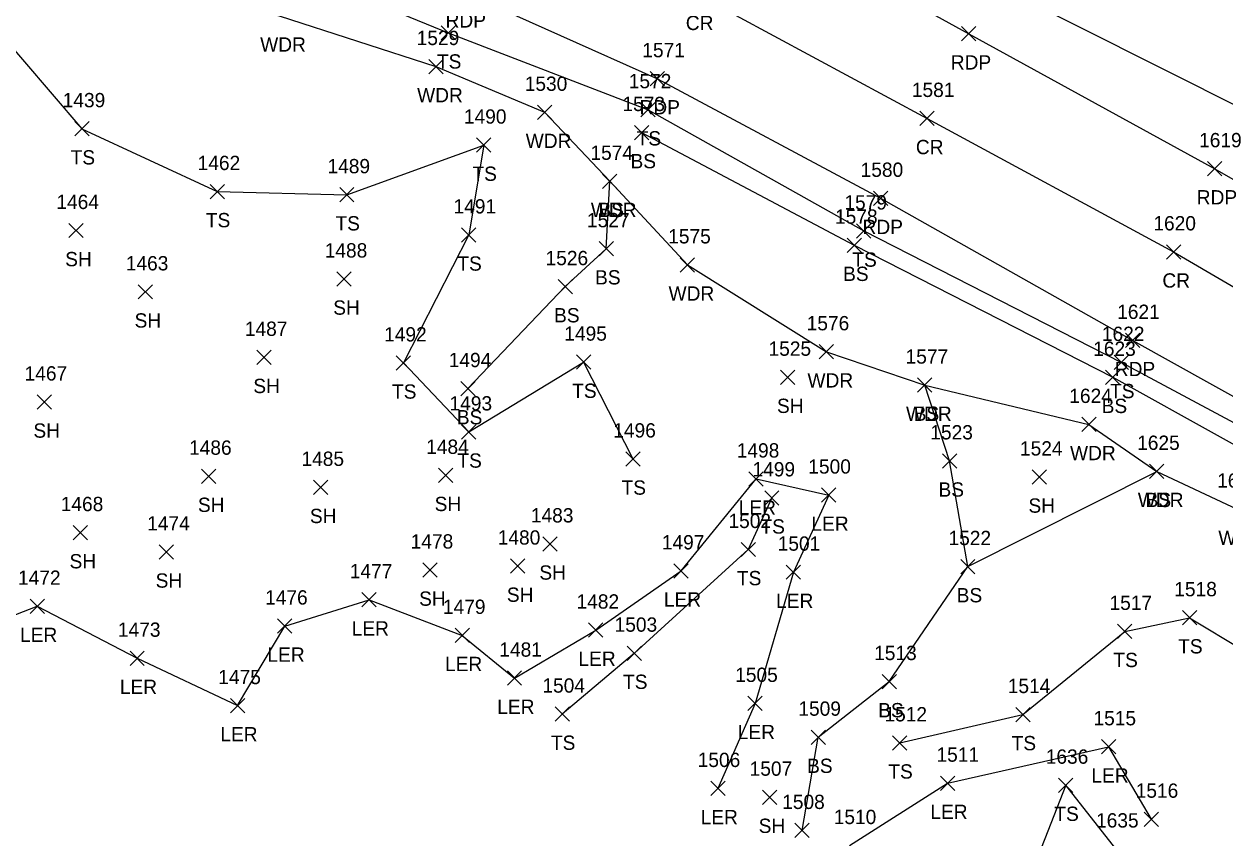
# Model space of a CAD drawing. Extents: x 1586965 to 1590952, y 716317 to 720029.
# Drawn here: x 1587807.3 to 1587975.1, y 719689.6 to 719803.4 of the extents above; entities that cross this region are included whole.
import ezdxf

# ---------------------------------------------------------------- set-up
doc = ezdxf.new("R2010")
doc.units = 0
for name, color, linetype in [('L_A', 7, 'Continuous'), ('L_I', 7, 'Continuous'), ('L_TIC', 7, 'Continuous'), ('LARO', 7, 'Continuous'), ('LAWA', 7, 'Continuous'), ('LELB', 7, 'Continuous'), ('P_A', 7, 'Continuous'), ('P_I', 7, 'Continuous'), ('P_TIC', 7, 'Continuous'), ('PET', 7, 'Continuous'), ('PRC', 7, 'Continuous')]:
    doc.layers.add(name, color=color, linetype=linetype)

msp = doc.modelspace()

# ---------------------------------------------------------------- linework, layer by layer
at = {"layer": 'L_TIC'}
for points in [[(1587865.59, 719801.16), (1587867.59, 719803.16)], [(1587867.59, 719801.16), (1587865.59, 719803.16)], [(1587863.87, 719796.45), (1587865.87, 719798.45)], [(1587865.87, 719796.45), (1587863.87, 719798.45)], [(1587879.05, 719790.05), (1587881.05, 719792.05)], [(1587881.05, 719790.05), (1587879.05, 719792.05)], [(1587893.5, 719790.41), (1587895.5, 719792.41)], [(1587895.5, 719790.41), (1587893.5, 719792.41)], [(1587814.4, 719787.75), (1587816.4, 719789.75)], [(1587816.4, 719787.75), (1587814.4, 719789.75)], [(1587892.61, 719787.22), (1587894.61, 719789.22)], [(1587894.61, 719787.22), (1587892.61, 719789.22)], [(1587870.55, 719785.46), (1587872.55, 719787.46)], [(1587872.55, 719785.46), (1587870.55, 719787.46)], [(1587888.14, 719780.4), (1587890.14, 719782.4)], [(1587890.14, 719780.4), (1587888.14, 719782.4)], [(1587888.14, 719780.4), (1587890.14, 719782.4)], [(1587890.14, 719780.4), (1587888.14, 719782.4)], [(1587833.3, 719778.97), (1587835.3, 719780.97)], [(1587835.3, 719778.97), (1587833.3, 719780.97)], [(1587851.41, 719778.52), (1587853.41, 719780.52)], [(1587853.41, 719778.52), (1587851.41, 719780.52)], [(1587813.56, 719773.52), (1587815.56, 719775.52)], [(1587815.56, 719773.52), (1587813.56, 719775.52)], [(1587868.44, 719772.9), (1587870.44, 719774.9)], [(1587870.44, 719772.9), (1587868.44, 719774.9)], [(1587923.64, 719773.45), (1587925.64, 719775.45)], [(1587925.64, 719773.45), (1587923.64, 719775.45)], [(1587887.66, 719770.97), (1587889.66, 719772.97)], [(1587889.66, 719770.97), (1587887.66, 719772.97)], [(1587922.32, 719771.46), (1587924.32, 719773.46)], [(1587924.32, 719771.46), (1587922.32, 719773.46)], [(1587899.01, 719768.71), (1587901.01, 719770.71)], [(1587901.01, 719768.71), (1587899.01, 719770.71)], [(1587851.02, 719766.74), (1587853.02, 719768.74)], [(1587853.02, 719766.74), (1587851.02, 719768.74)], [(1587881.93, 719765.67), (1587883.93, 719767.67)], [(1587883.93, 719765.67), (1587881.93, 719767.67)], [(1587823.26, 719764.94), (1587825.26, 719766.94)], [(1587825.26, 719764.94), (1587823.26, 719766.94)], [(1587839.85, 719755.78), (1587841.85, 719757.78)], [(1587841.85, 719755.78), (1587839.85, 719757.78)], [(1587918.42, 719756.56), (1587920.42, 719758.56)], [(1587920.42, 719756.56), (1587918.42, 719758.56)], [(1587859.31, 719755), (1587861.31, 719757)], [(1587861.31, 719755), (1587859.31, 719757)], [(1587884.49, 719755.11), (1587886.49, 719757.11)], [(1587886.49, 719755.11), (1587884.49, 719757.11)], [(1587959.66, 719755.07), (1587961.66, 719757.07)], [(1587961.66, 719755.07), (1587959.66, 719757.07)], [(1587913.03, 719753), (1587915.03, 719755)], [(1587915.03, 719753), (1587913.03, 719755)], [(1587958.45, 719752.99), (1587960.45, 719754.99)], [(1587960.45, 719752.99), (1587958.45, 719754.99)], [(1587868.34, 719751.41), (1587870.34, 719753.41)], [(1587870.34, 719751.41), (1587868.34, 719753.41)], [(1587932.18, 719751.9), (1587934.18, 719753.9)], [(1587934.18, 719751.9), (1587932.18, 719753.9)], [(1587932.18, 719751.9), (1587934.18, 719753.9)], [(1587934.18, 719751.9), (1587932.18, 719753.9)], [(1587809.12, 719749.54), (1587811.12, 719751.54)], [(1587811.12, 719749.54), (1587809.12, 719751.54)], [(1587955.11, 719746.4), (1587957.11, 719748.4)], [(1587957.11, 719746.4), (1587955.11, 719748.4)], [(1587868.45, 719745.35), (1587870.45, 719747.35)], [(1587870.45, 719745.35), (1587868.45, 719747.35)], [(1587891.39, 719741.57), (1587893.39, 719743.57)], [(1587893.39, 719741.57), (1587891.39, 719743.57)], [(1587935.65, 719741.3), (1587937.65, 719743.3)], [(1587937.65, 719741.3), (1587935.65, 719743.3)], [(1587832.11, 719739.16), (1587834.11, 719741.16)], [(1587834.11, 719739.16), (1587832.11, 719741.16)], [(1587865.2, 719739.28), (1587867.2, 719741.28)], [(1587867.2, 719739.28), (1587865.2, 719741.28)], [(1587948.17, 719739.05), (1587950.17, 719741.05)], [(1587950.17, 719739.05), (1587948.17, 719741.05)], [(1587964.59, 719739.84), (1587966.59, 719741.84)], [(1587966.59, 719739.84), (1587964.59, 719741.84)], [(1587964.59, 719739.84), (1587966.59, 719741.84)], [(1587966.59, 719739.84), (1587964.59, 719741.84)], [(1587847.76, 719737.6), (1587849.76, 719739.6)], [(1587849.76, 719737.6), (1587847.76, 719739.6)], [(1587908.6, 719738.77), (1587910.6, 719740.77)], [(1587910.6, 719738.77), (1587908.6, 719740.77)], [(1587910.8, 719736.13), (1587912.8, 719738.13)], [(1587912.8, 719736.13), (1587910.8, 719738.13)], [(1587918.76, 719736.52), (1587920.76, 719738.52)], [(1587920.76, 719736.52), (1587918.76, 719738.52)], [(1587814.17, 719731.27), (1587816.17, 719733.27)], [(1587816.17, 719731.27), (1587814.17, 719733.27)], [(1587879.82, 719729.69), (1587881.82, 719731.69)], [(1587881.82, 719729.69), (1587879.82, 719731.69)], [(1587907.51, 719728.91), (1587909.51, 719730.91)], [(1587909.51, 719728.91), (1587907.51, 719730.91)], [(1587826.2, 719728.57), (1587828.2, 719730.57)], [(1587828.2, 719728.57), (1587826.2, 719730.57)], [(1587863.02, 719726.04), (1587865.02, 719728.04)], [(1587865.02, 719726.04), (1587863.02, 719728.04)], [(1587875.28, 719726.59), (1587877.28, 719728.59)], [(1587877.28, 719726.59), (1587875.28, 719728.59)], [(1587898.12, 719725.92), (1587900.12, 719727.92)], [(1587900.12, 719725.92), (1587898.12, 719727.92)], [(1587913.82, 719725.74), (1587915.82, 719727.74)], [(1587915.82, 719725.74), (1587913.82, 719727.74)], [(1587938.19, 719726.52), (1587940.19, 719728.52)], [(1587940.19, 719726.52), (1587938.19, 719728.52)], [(1587938.19, 719726.52), (1587940.19, 719728.52)], [(1587940.19, 719726.52), (1587938.19, 719728.52)], [(1587808.15, 719720.97), (1587810.15, 719722.97)], [(1587810.15, 719720.97), (1587808.15, 719722.97)], [(1587854.51, 719721.88), (1587856.51, 719723.88)], [(1587856.51, 719721.88), (1587854.51, 719723.88)], [(1587969.17, 719719.37), (1587971.17, 719721.37)], [(1587971.17, 719719.37), (1587969.17, 719721.37)], [(1587842.73, 719718.21), (1587844.73, 719720.21)], [(1587844.73, 719718.21), (1587842.73, 719720.21)], [(1587886.2, 719717.64), (1587888.2, 719719.64)], [(1587888.2, 719717.64), (1587886.2, 719719.64)], [(1587960.12, 719717.46), (1587962.12, 719719.46)], [(1587962.12, 719717.46), (1587960.12, 719719.46)], [(1587867.54, 719716.9), (1587869.54, 719718.9)], [(1587869.54, 719716.9), (1587867.54, 719718.9)], [(1587822.11, 719713.7), (1587824.11, 719715.7)], [(1587824.11, 719713.7), (1587822.11, 719715.7)], [(1587891.6, 719714.41), (1587893.6, 719716.41)], [(1587893.6, 719714.41), (1587891.6, 719716.41)], [(1587874.84, 719710.92), (1587876.84, 719712.92)], [(1587876.84, 719710.92), (1587874.84, 719712.92)], [(1587927.22, 719710.44), (1587929.22, 719712.44)], [(1587929.22, 719710.44), (1587927.22, 719712.44)], [(1587836.15, 719707.08), (1587838.15, 719709.08)], [(1587838.15, 719707.08), (1587836.15, 719709.08)], [(1587908.45, 719707.39), (1587910.45, 719709.39)], [(1587910.45, 719707.39), (1587908.45, 719709.39)], [(1587881.52, 719705.89), (1587883.52, 719707.89)], [(1587883.52, 719705.89), (1587881.52, 719707.89)], [(1587945.9, 719705.83), (1587947.9, 719707.83)], [(1587947.9, 719705.83), (1587945.9, 719707.83)], [(1587917.29, 719702.66), (1587919.29, 719704.66)], [(1587919.29, 719702.66), (1587917.29, 719704.66)], [(1587928.67, 719701.87), (1587930.67, 719703.87)], [(1587930.67, 719701.87), (1587928.67, 719703.87)], [(1587957.87, 719701.32), (1587959.87, 719703.32)], [(1587959.87, 719701.32), (1587957.87, 719703.32)], [(1587903.27, 719695.49), (1587905.27, 719697.49)], [(1587905.27, 719695.49), (1587903.27, 719697.49)], [(1587935.37, 719696.23), (1587937.37, 719698.23)], [(1587937.37, 719696.23), (1587935.37, 719698.23)], [(1587951.87, 719695.95), (1587953.87, 719697.95)], [(1587953.87, 719695.95), (1587951.87, 719697.95)], [(1587910.48, 719694.27), (1587912.48, 719696.27)], [(1587912.48, 719694.27), (1587910.48, 719696.27)], [(1587963.83, 719691.19), (1587965.83, 719693.19)], [(1587965.83, 719691.19), (1587963.83, 719693.19)], [(1587915.02, 719689.62), (1587917.02, 719691.62)], [(1587917.02, 719689.62), (1587915.02, 719691.62)]]:
    msp.add_lwpolyline(points, dxfattribs=at)
at = {"layer": 'LARO'}
for points in [[(1587800.16, 719718.5), (1587809.15, 719721.97), (1587823.11, 719714.7), (1587837.15, 719708.08), (1587843.73, 719719.21), (1587855.51, 719722.88), (1587868.54, 719717.9), (1587875.84, 719711.92), (1587887.2, 719718.64), (1587899.12, 719726.92), (1587909.6, 719739.77), (1587919.76, 719737.52), (1587914.82, 719726.74), (1587909.45, 719708.39), (1587904.27, 719696.49)], [(1587922.67, 719688.51), (1587936.37, 719697.23), (1587958.87, 719702.32), (1587964.83, 719692.19)]]:
    msp.add_lwpolyline(points, dxfattribs=at)
at = {"layer": 'LAWA'}
msp.add_lwpolyline([(1587792.66, 719819.32), (1587813.67, 719812.11), (1587842.94, 719804.53), (1587864.87, 719797.45), (1587880.05, 719791.05), (1587889.14, 719781.4), (1587900.01, 719769.71), (1587919.42, 719757.56), (1587933.18, 719752.9), (1587956.11, 719747.4), (1587965.59, 719740.84), (1587976.83, 719735.56), (1587989.17, 719727.65), (1588001.34, 719721.18), (1588025.48, 719708.03), (1588041.3, 719690.98), (1588054.29, 719686.88), (1588082.98, 719668.28), (1588093.79, 719656.56), (1588121.25, 719657.28), (1588128.24, 719644.6), (1588131.95, 719613.69), (1588124.34, 719595.05)], dxfattribs=at)
at = {"layer": 'LELB'}
for points in [[(1587785.92, 719905.04), (1587790.72, 719880.4), (1587795.97, 719870.23), (1587799.98, 719865.36), (1587821.67, 719859.64), (1587858.86, 719846.91), (1587879.62, 719839.86), (1587909.63, 719826.79), (1587942.7, 719809.1), (1587978.02, 719791.31), (1588014.84, 719771.38), (1588022.21, 719777.17), (1588033.93, 719779.83), (1588041.77, 719778.33), (1588050.57, 719796.18), (1588059.09, 719817.76), (1588066.51, 719841.34), (1588067.52, 719856.77)], [(1587785.92, 719905.04), (1587790.72, 719880.4), (1587795.97, 719870.23), (1587799.98, 719865.36), (1587821.67, 719859.64), (1587858.86, 719846.91), (1587879.62, 719839.86), (1587909.63, 719826.79), (1587942.7, 719809.1), (1587978.02, 719791.31), (1588014.84, 719771.38), (1588022.21, 719777.17), (1588033.93, 719779.83), (1588041.77, 719778.33), (1588050.57, 719796.18), (1588059.09, 719817.76), (1588066.51, 719841.34), (1588067.52, 719856.77)], [(1587769.54, 719828.25), (1587817.81, 719818.92), (1587845.39, 719810.87), (1587866.59, 719802.16), (1587894.5, 719791.41), (1587924.64, 719774.45), (1587960.66, 719756.07), (1587994.24, 719738.05), (1588029.81, 719715.93), (1588049.13, 719705.79), (1588061.35, 719699.86), (1588090.7, 719682.25), (1588125.12, 719667.08), (1588163.84, 719653.66), (1588168.64, 719652.01), (1588170.5, 719647.84), (1588169.34, 719638.56), (1588158.94, 719617.68), (1588144.69, 719590.38)], [(1587769.54, 719828.25), (1587817.81, 719818.92), (1587845.39, 719810.87), (1587866.59, 719802.16), (1587894.5, 719791.41), (1587924.64, 719774.45), (1587960.66, 719756.07), (1587994.24, 719738.05), (1588029.81, 719715.93), (1588049.13, 719705.79), (1588061.35, 719699.86), (1588090.7, 719682.25), (1588125.12, 719667.08), (1588163.84, 719653.66), (1588168.64, 719652.01), (1588170.5, 719647.84), (1588169.34, 719638.56), (1588158.94, 719617.68), (1588144.69, 719590.38)], [(1587802.88, 719803.26), (1587815.4, 719788.75), (1587834.3, 719779.97), (1587852.41, 719779.52), (1587871.55, 719786.46), (1587869.44, 719773.9), (1587860.31, 719756), (1587869.45, 719746.35), (1587885.49, 719756.11), (1587892.39, 719742.57)], [(1587802.88, 719803.26), (1587815.4, 719788.75), (1587834.3, 719779.97), (1587852.41, 719779.52), (1587871.55, 719786.46), (1587869.44, 719773.9), (1587860.31, 719756), (1587869.45, 719746.35), (1587885.49, 719756.11), (1587892.39, 719742.57)], [(1587893.61, 719788.22), (1587923.32, 719772.46), (1587959.45, 719753.99), (1587990.31, 719736.86), (1587992.49, 719736.59), (1587993.47, 719735.49), (1587996.7, 719733.15), (1588001.37, 719729.89), (1588028.07, 719713.52), (1588047.21, 719701.72), (1588059.27, 719695.66), (1588101.54, 719672.79), (1588123.97, 719663.55), (1588153.31, 719655.21), (1588167.62, 719650.14)], [(1587893.61, 719788.22), (1587923.32, 719772.46), (1587959.45, 719753.99), (1587990.31, 719736.86), (1587992.49, 719736.59), (1587993.47, 719735.49), (1587996.7, 719733.15), (1588001.37, 719729.89), (1588028.07, 719713.52), (1588047.21, 719701.72), (1588059.27, 719695.66), (1588101.54, 719672.79), (1588123.97, 719663.55), (1588153.31, 719655.21), (1588167.62, 719650.14)], [(1587869.34, 719752.41), (1587882.93, 719766.67), (1587888.66, 719771.97), (1587889.14, 719781.4)], [(1587869.34, 719752.41), (1587882.93, 719766.67), (1587888.66, 719771.97), (1587889.14, 719781.4)], [(1587939.19, 719727.52), (1587936.65, 719742.3), (1587933.18, 719752.9)], [(1587939.19, 719727.52), (1587936.65, 719742.3), (1587933.18, 719752.9)], [(1587916.02, 719690.62), (1587918.29, 719703.66), (1587928.22, 719711.44), (1587939.19, 719727.52), (1587965.59, 719740.84)], [(1587916.02, 719690.62), (1587918.29, 719703.66), (1587928.22, 719711.44), (1587939.19, 719727.52), (1587965.59, 719740.84)], [(1587911.8, 719737.13), (1587908.51, 719729.91), (1587892.6, 719715.41), (1587882.52, 719706.89)], [(1587911.8, 719737.13), (1587908.51, 719729.91), (1587892.6, 719715.41), (1587882.52, 719706.89)], [(1587929.67, 719702.87), (1587946.9, 719706.83), (1587961.12, 719718.46), (1587970.17, 719720.37), (1587977.76, 719715.8), (1587982.6, 719715.23), (1587982.22, 719704.04)], [(1587929.67, 719702.87), (1587946.9, 719706.83), (1587961.12, 719718.46), (1587970.17, 719720.37), (1587977.76, 719715.8), (1587982.6, 719715.23), (1587982.22, 719704.04)], [(1587969.24, 719671.97), (1587959.85, 719688.03), (1587952.87, 719696.95), (1587946.92, 719681.69)], [(1587969.24, 719671.97), (1587959.85, 719688.03), (1587952.87, 719696.95), (1587946.92, 719681.69)]]:
    msp.add_lwpolyline(points, dxfattribs=at)
at = {"layer": 'P_TIC'}
for points in [[(1587938.32, 719801.03), (1587940.32, 719803.03)], [(1587940.32, 719801.03), (1587938.32, 719803.03)], [(1587894.82, 719794.75), (1587896.82, 719796.75)], [(1587896.82, 719794.75), (1587894.82, 719796.75)], [(1587932.49, 719789.19), (1587934.49, 719791.19)], [(1587934.49, 719789.19), (1587932.49, 719791.19)], [(1587972.69, 719782.16), (1587974.69, 719784.16)], [(1587974.69, 719782.16), (1587972.69, 719784.16)], [(1587925.99, 719778.02), (1587927.99, 719780.02)], [(1587927.99, 719778.02), (1587925.99, 719780.02)], [(1587966.95, 719770.53), (1587968.95, 719772.53)], [(1587968.95, 719770.53), (1587966.95, 719772.53)], [(1587961.24, 719758.15), (1587963.24, 719760.15)], [(1587963.24, 719758.15), (1587961.24, 719760.15)]]:
    msp.add_lwpolyline(points, dxfattribs=at)
at = {"layer": 'PET'}
for points in [[(1587795.98, 719858.74), (1587820.3, 719853.13), (1587857.37, 719841.42), (1587877.69, 719833.83), (1587907.04, 719819.84), (1587939.32, 719802.03), (1587973.69, 719783.16), (1588008.21, 719763.34), (1588019.61, 719757.58), (1588045.18, 719744.38), (1588072.84, 719731.02), (1588081.8, 719723.85), (1588104.43, 719712.22), (1588133.68, 719697.26), (1588170.87, 719681.39), (1588198.42, 719670.99), (1588228.28, 719659.25)], [(1587769.59, 719834.05), (1587819.16, 719826.14), (1587848.36, 719816.77), (1587868.73, 719807.9), (1587895.82, 719795.75), (1587926.99, 719779.02), (1587962.24, 719759.15), (1587995.65, 719740.56), (1588031.83, 719719.54), (1588060.89, 719703.68), (1588093.53, 719688.06), (1588127.35, 719672.7), (1588165.1, 719657.02), (1588195.68, 719645.12), (1588212.38, 719637.86), (1588219.86, 719635.29)]]:
    msp.add_lwpolyline(points, dxfattribs=at)
at = {"layer": 'PRC'}
msp.add_lwpolyline([(1587770.57, 719846.88), (1587822.37, 719838.71), (1587852.49, 719828.95), (1587873.58, 719820.04), (1587901.35, 719807.55), (1587933.49, 719790.19), (1587967.95, 719771.53), (1588001.84, 719751.71), (1588038.72, 719731.7), (1588068.79, 719715.56), (1588099.02, 719700.65), (1588127.2, 719686.75), (1588167.73, 719669.46), (1588194.58, 719658.84), (1588224.51, 719647.27)], dxfattribs=at)
msp.add_lwpolyline([(1587770.57, 719846.88), (1587822.37, 719838.71), (1587852.49, 719828.95), (1587873.58, 719820.04), (1587901.35, 719807.55), (1587933.49, 719790.19), (1587967.95, 719771.53), (1588001.84, 719751.71), (1588038.72, 719731.7), (1588068.79, 719715.56), (1588099.02, 719700.65), (1588127.2, 719686.75), (1588167.73, 719669.46), (1588194.58, 719658.84), (1588224.51, 719647.27)], dxfattribs=at)

# ---------------------------------------------------------------- texts
at = {"layer": 'L_A'}
for s, p in [('WDR', (1587840.3, 719799.53)), ('TS', (1587865, 719797.16)), ('WDR', (1587862.23, 719792.45)), ('WDR', (1587877.41, 719786.05)), ('TS', (1587892.91, 719786.41)), ('TS', (1587813.81, 719783.75)), ('BS', (1587892.05, 719783.22)), ('TS', (1587869.96, 719781.46)), ('WDR', (1587886.51, 719776.4)), ('BS', (1587887.58, 719776.4)), ('TS', (1587832.71, 719774.97)), ('TS', (1587850.82, 719774.52)), ('SH', (1587813.05, 719769.52)), ('TS', (1587923.05, 719769.45)), ('TS', (1587867.85, 719768.9)), ('BS', (1587921.76, 719767.46)), ('BS', (1587887.1, 719766.97)), ('WDR', (1587897.37, 719764.71)), ('SH', (1587850.51, 719762.74)), ('SH', (1587822.75, 719760.94)), ('BS', (1587881.37, 719761.67)), ('WDR', (1587916.78, 719752.56)), ('SH', (1587839.34, 719751.78)), ('TS', (1587858.72, 719751)), ('TS', (1587883.9, 719751.11)), ('TS', (1587959.07, 719751.07)), ('SH', (1587912.52, 719749)), ('BS', (1587957.89, 719748.99)), ('BS', (1587867.78, 719747.41)), ('WDR', (1587930.55, 719747.9)), ('BS', (1587931.62, 719747.9)), ('SH', (1587808.61, 719745.54)), ('WDR', (1587953.47, 719742.4)), ('TS', (1587867.86, 719741.35)), ('TS', (1587890.8, 719737.57)), ('BS', (1587935.09, 719737.3)), ('WDR', (1587962.95, 719735.84)), ('BS', (1587964.03, 719735.84)), ('SH', (1587831.6, 719735.16)), ('SH', (1587864.68, 719735.28)), ('LER', (1587907.18, 719734.77)), ('SH', (1587947.66, 719735.05)), ('SH', (1587847.25, 719733.6)), ('TS', (1587910.21, 719732.13)), ('LER', (1587917.34, 719732.52)), ('WDR', (1587974.19, 719730.56)), ('SH', (1587813.66, 719727.27)), ('SH', (1587879.31, 719725.69)), ('SH', (1587825.69, 719724.57)), ('TS', (1587906.92, 719724.91)), ('SH', (1587862.51, 719722.04)), ('SH', (1587874.77, 719722.59)), ('BS', (1587937.63, 719722.52)), ('BS', (1587937.63, 719722.52)), ('LER', (1587896.71, 719721.92)), ('LER', (1587912.4, 719721.74)), ('LER', (1587853.09, 719717.88)), ('LER', (1587806.74, 719716.97)), ('TS', (1587968.58, 719715.37)), ('LER', (1587841.32, 719714.21)), ('LER', (1587884.78, 719713.64)), ('LER', (1587866.13, 719712.9)), ('TS', (1587959.53, 719713.46)), ('TS', (1587891.01, 719710.41)), ('LER', (1587820.69, 719709.7)), ('LER', (1587873.43, 719706.92)), ('BS', (1587926.66, 719706.44)), ('LER', (1587834.73, 719703.08)), ('TS', (1587880.93, 719701.89)), ('LER', (1587907.04, 719703.39)), ('TS', (1587945.31, 719701.83)), ('BS', (1587916.73, 719698.66)), ('TS', (1587928.08, 719697.87)), ('LER', (1587956.46, 719697.32)), ('LER', (1587933.95, 719692.23)), ('TS', (1587951.28, 719691.95)), ('LER', (1587901.85, 719691.49)), ('SH', (1587909.96, 719690.27))]:
    msp.add_text(s, height=2, dxfattribs=at).set_placement(p)
at = {"layer": 'L_I'}
for s, p in [('1529', (1587862.17, 719800.45)), ('1572', (1587891.81, 719794.41)), ('1530', (1587877.27, 719794.05)), ('1439', (1587812.7, 719791.75)), ('1573', (1587890.92, 719791.22)), ('1490', (1587868.77, 719789.46)), ('1574', (1587886.45, 719784.4)), ('1574', (1587886.45, 719784.4)), ('1462', (1587831.56, 719782.97)), ('1489', (1587849.71, 719782.52)), ('1464', (1587811.82, 719777.52)), ('1579', (1587921.94, 719777.45)), ('1491', (1587867.32, 719776.9)), ('1527', (1587885.97, 719774.97)), ('1578', (1587920.63, 719775.46)), ('1575', (1587897.32, 719772.71)), ('1488', (1587849.32, 719770.74)), ('1526', (1587880.18, 719769.67)), ('1463', (1587821.52, 719768.94)), ('1487', (1587838.16, 719759.78)), ('1492', (1587857.62, 719759)), ('1495', (1587882.8, 719759.11)), ('1576', (1587916.67, 719760.56)), ('1622', (1587957.92, 719759.07)), ('1525', (1587911.34, 719757)), ('1577', (1587930.49, 719755.9)), ('1577', (1587930.49, 719755.9)), ('1623', (1587956.71, 719756.99)), ('1494', (1587866.65, 719755.41)), ('1467', (1587807.38, 719753.54)), ('1493', (1587866.76, 719749.35)), ('1624', (1587953.37, 719750.4)), ('1496', (1587889.64, 719745.57)), ('1523', (1587933.95, 719745.3)), ('1625', (1587962.85, 719743.84)), ('1625', (1587962.85, 719743.84)), ('1486', (1587830.36, 719743.16)), ('1484', (1587863.5, 719743.28)), ('1498', (1587906.9, 719742.77)), ('1524', (1587946.48, 719743.05)), ('1485', (1587846.07, 719741.6)), ('1500', (1587916.9, 719740.52)), ('1499', (1587909.1, 719740.13)), ('1626', (1587974.03, 719738.56)), ('1468', (1587812.43, 719735.27)), ('1474', (1587824.51, 719732.57)), ('1483', (1587878.13, 719733.69)), ('1502', (1587905.74, 719732.91)), ('1480', (1587873.5, 719730.59)), ('1522', (1587936.49, 719730.52)), ('1522', (1587936.49, 719730.52)), ('1478', (1587861.33, 719730.04)), ('1497', (1587896.43, 719729.92)), ('1501', (1587912.62, 719729.74)), ('1477', (1587852.82, 719725.88)), ('1472', (1587806.46, 719724.97)), ('1476', (1587840.99, 719722.21)), ('1518', (1587968.04, 719723.37)), ('1479', (1587865.84, 719720.9)), ('1482', (1587884.51, 719721.64)), ('1517', (1587958.99, 719721.46)), ('1473', (1587820.42, 719717.7)), ('1503', (1587889.83, 719718.41)), ('1481', (1587873.72, 719714.92)), ('1513', (1587926.1, 719714.44)), ('1475', (1587834.45, 719711.08)), ('1505', (1587906.68, 719711.39)), ('1504', (1587879.74, 719709.89)), ('1514', (1587944.77, 719709.83)), ('1509', (1587915.51, 719706.66)), ('1512', (1587927.54, 719705.87)), ('1515', (1587956.75, 719705.32)), ('1511', (1587934.81, 719700.23)), ('1506', (1587901.44, 719699.49)), ('1636', (1587950.08, 719699.95)), ('1507', (1587908.7, 719698.27)), ('1516', (1587962.65, 719695.19)), ('1508', (1587913.25, 719693.62)), ('1510', (1587920.45, 719691.51)), ('1635', (1587957.11, 719691.03))]:
    msp.add_text(s, height=2, dxfattribs=at).set_placement(p)
at = {"layer": 'P_A'}
for s, p in [('RDP', (1587866.21, 719802.9)), ('CR', (1587899.78, 719802.55)), ('RDP', (1587936.81, 719797.03)), ('RDP', (1587893.31, 719790.75)), ('CR', (1587931.93, 719785.19)), ('RDP', (1587971.18, 719778.16)), ('RDP', (1587924.48, 719774.02)), ('CR', (1587966.38, 719766.53)), ('RDP', (1587959.73, 719754.15))]:
    msp.add_text(s, height=2, dxfattribs=at).set_placement(p)
at = {"layer": 'P_I'}
for s, p in [('1571', (1587893.7, 719798.75)), ('1581', (1587931.37, 719793.19)), ('1619', (1587971.51, 719786.16)), ('1580', (1587924.21, 719782.02)), ('1620', (1587965.12, 719774.53)), ('1621', (1587960.06, 719762.15))]:
    msp.add_text(s, height=2, dxfattribs=at).set_placement(p)

doc.saveas('drawing.dxf')
